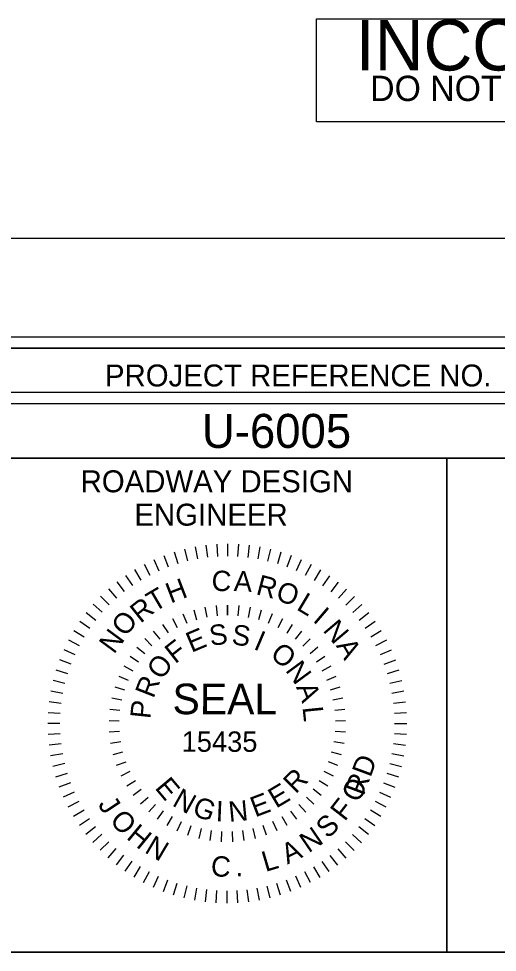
# Model space of a CAD drawing. Extents: x 1623313 to 1628771, y 891211 to 901910.
# Drawn here: x 1624782.4 to 1624891.5, y 901696.9 to 901909.5 of the extents above; entities that cross this region are included whole.
import ezdxf

# ---------------------------------------------------------------- set-up
doc = ezdxf.new("R2010")
doc.units = 0
for name, color, linetype in [('Old_Level_21', 7, 'Continuous'), ('Prop Plan Preparation Cover Label', 7, 'Continuous'), ('Scratch_Level_0', 7, 'Continuous'), ('Sheet Cutting Line CELL', 7, 'Continuous'), ('Sheet Data Field CELL', 7, 'Continuous'), ('Sheet Plot Border Inside CELL', 7, 'Continuous'), ('Sheet Plot Border Outside CELL', 7, 'Continuous'), ('Sheet Profile CELL', 7, 'Continuous'), ('Sheet Profile Grid Major CELL', 7, 'Continuous'), ('Sheet Profile Grid Minor CELL', 7, 'Continuous'), ('Sheet Sticker Exception Certification CELL', 7, 'Continuous')]:
    doc.layers.add(name, color=color, linetype=linetype)

msp = doc.modelspace()

# ---------------------------------------------------------------- linework, layer by layer
at = {"layer": 'Old_Level_21'}
for p, q in [((1624820.25, 901788.74), (1624820.9, 901786.03)), ((1624822.66, 901789.26), (1624823.16, 901786.51)), ((1624825.1, 901789.62), (1624825.43, 901786.86)), ((1624827.56, 901789.84), (1624827.73, 901787.06)), ((1624830.03, 901789.91), (1624830.03, 901787.13)), ((1624832.51, 901789.84), (1624832.33, 901787.05)), ((1624834.96, 901789.61), (1624834.63, 901786.84)), ((1624837.41, 901789.24), (1624836.9, 901786.49)), ((1624839.82, 901788.71), (1624839.15, 901786.01)), ((1624813.24, 901786.33), (1624814.38, 901783.79)), ((1624815.53, 901787.28), (1624816.51, 901784.67)), ((1624817.86, 901788.08), (1624818.69, 901785.41)), ((1624842.2, 901788.05), (1624841.37, 901785.38)), ((1624844.54, 901787.24), (1624843.54, 901784.63)), ((1624846.82, 901786.28), (1624845.67, 901783.75)), ((1624811.02, 901785.26), (1624812.31, 901782.78)), ((1624849.04, 901785.2), (1624847.74, 901782.73)), ((1624806.79, 901782.71), (1624808.37, 901780.41)), ((1624808.86, 901784.04), (1624810.3, 901781.66)), ((1624851.19, 901783.99), (1624849.74, 901781.6)), ((1624853.26, 901782.64), (1624851.67, 901780.35)), ((1624804.8, 901781.25), (1624806.51, 901779.05)), ((1624855.25, 901781.18), (1624853.53, 901778.98)), ((1624801.09, 901777.97), (1624803.06, 901776)), ((1624802.89, 901779.66), (1624804.74, 901777.58)), ((1624857.15, 901779.59), (1624855.29, 901777.51)), ((1624858.94, 901777.89), (1624856.97, 901775.92)), ((1624799.4, 901776.18), (1624801.48, 901774.33)), ((1624827.41, 901775.85), (1624827.63, 901773.53)), ((1624830.01, 901775.97), (1624830.01, 901773.65)), ((1624830.01, 901773.65), (1624830.01, 901775.97)), ((1624832.62, 901775.84), (1624832.39, 901773.53)), ((1624860.63, 901776.09), (1624858.54, 901774.25)), ((1624797.81, 901774.28), (1624800, 901772.56)), ((1624819.84, 901773.99), (1624820.72, 901771.84)), ((1624822.31, 901774.86), (1624822.96, 901772.63)), ((1624824.84, 901775.47), (1624825.28, 901773.19)), ((1624835.19, 901775.46), (1624834.75, 901773.18)), ((1624837.72, 901774.83), (1624837.06, 901772.61)), ((1624840.18, 901773.97), (1624839.3, 901771.81)), ((1624862.21, 901774.19), (1624860.02, 901772.48)), ((1624796.35, 901772.29), (1624798.64, 901770.71)), ((1624815.23, 901771.58), (1624816.5, 901769.63)), ((1624817.48, 901772.9), (1624818.56, 901770.84)), ((1624842.54, 901772.86), (1624841.46, 901770.81)), ((1624844.78, 901771.54), (1624843.51, 901769.6)), ((1624863.67, 901772.2), (1624861.38, 901770.62)), ((1624795, 901770.22), (1624797.38, 901768.77)), ((1624813.12, 901770.05), (1624814.58, 901768.24)), ((1624846.89, 901770.01), (1624845.43, 901768.19)), ((1624865.01, 901770.12), (1624862.63, 901768.68)), ((1624793.78, 901768.07), (1624796.25, 901766.77)), ((1624811.17, 901768.33), (1624812.8, 901766.66)), ((1624848.84, 901768.27), (1624847.21, 901766.61)), ((1624866.23, 901767.97), (1624863.75, 901766.68)), ((1624792.7, 901765.85), (1624795.24, 901764.7)), ((1624809.4, 901766.42), (1624811.17, 901764.92)), ((1624850.61, 901766.37), (1624848.83, 901764.87)), ((1624867.3, 901765.74), (1624864.76, 901764.61)), ((1624791.75, 901763.57), (1624794.36, 901762.57)), ((1624807.81, 901764.36), (1624809.72, 901763.03)), ((1624852.19, 901764.3), (1624850.27, 901762.97)), ((1624868.25, 901763.46), (1624865.64, 901762.47)), ((1624790.94, 901761.24), (1624793.6, 901760.4)), ((1624806.44, 901762.15), (1624808.46, 901761.01)), ((1624853.56, 901762.08), (1624851.53, 901760.95)), ((1624869.05, 901761.13), (1624866.38, 901760.3)), ((1624790.27, 901758.85), (1624792.98, 901758.19)), ((1624805.27, 901759.81), (1624807.4, 901758.88)), ((1624854.71, 901759.74), (1624852.58, 901758.82)), ((1624869.71, 901758.74), (1624867, 901758.08)), ((1624804.35, 901757.37), (1624806.56, 901756.66)), ((1624855.63, 901757.3), (1624853.42, 901756.59)), ((1624789.75, 901756.44), (1624792.49, 901755.93)), ((1624803.66, 901754.86), (1624805.93, 901754.36)), ((1624856.31, 901754.79), (1624854.04, 901754.29)), ((1624870.22, 901756.33), (1624867.48, 901755.83)), ((1624789.38, 901754), (1624792.14, 901753.66)), ((1624803.22, 901752.3), (1624805.52, 901752.02)), ((1624856.74, 901752.22), (1624854.44, 901751.95)), ((1624870.59, 901753.88), (1624867.82, 901753.55)), ((1624789.15, 901751.54), (1624791.93, 901751.37)), ((1624870.81, 901751.42), (1624868.03, 901751.26)), ((1624789.07, 901749.07), (1624791.86, 901749.06)), ((1624803.03, 901749.7), (1624805.35, 901749.64)), ((1624856.93, 901749.62), (1624854.61, 901749.57)), ((1624870.88, 901748.95), (1624868.09, 901748.96)), ((1624789.14, 901746.59), (1624791.93, 901746.76)), ((1624803.08, 901747.09), (1624805.4, 901747.26)), ((1624856.86, 901747.02), (1624854.55, 901747.19)), ((1624870.8, 901746.48), (1624868.02, 901746.65)), ((1624789.37, 901744.13), (1624792.13, 901744.47)), ((1624803.4, 901744.51), (1624805.69, 901744.9)), ((1624854.27, 901744.91), (1624856.56, 901744.52)), ((1624870.58, 901744.02), (1624867.81, 901744.36)), ((1624789.73, 901741.69), (1624792.47, 901742.19)), ((1624803.95, 901741.96), (1624806.19, 901742.57)), ((1624855.98, 901741.89), (1624853.74, 901742.5)), ((1624870.2, 901741.58), (1624867.46, 901742.08)), ((1624790.25, 901739.28), (1624792.95, 901739.94)), ((1624804.76, 901739.48), (1624806.93, 901740.3)), ((1624855.17, 901739.41), (1624853, 901740.24)), ((1624869.68, 901739.17), (1624866.98, 901739.83)), ((1624790.9, 901736.89), (1624793.57, 901737.72)), ((1624805.8, 901737.1), (1624807.88, 901738.12)), ((1624854.13, 901737.03), (1624852.05, 901738.06)), ((1624869.02, 901736.78), (1624866.35, 901737.62)), ((1624791.71, 901734.56), (1624794.32, 901735.54)), ((1624807.05, 901734.82), (1624809.03, 901736.04)), ((1624852.86, 901734.75), (1624850.89, 901735.98)), ((1624868.21, 901734.45), (1624865.6, 901735.45)), ((1624792.65, 901732.27), (1624795.2, 901733.41)), ((1624808.53, 901732.67), (1624810.38, 901734.08)), ((1624851.38, 901732.61), (1624849.53, 901734.02)), ((1624867.25, 901732.17), (1624864.71, 901733.32)), ((1624793.73, 901730.05), (1624796.2, 901731.34)), ((1624810.21, 901730.68), (1624811.91, 901732.25)), ((1624849.69, 901730.62), (1624848, 901732.2)), ((1624866.17, 901729.95), (1624863.7, 901731.25)), ((1624794.94, 901727.89), (1624797.33, 901729.34)), ((1624812.07, 901728.86), (1624813.62, 901730.59)), ((1624814.1, 901727.22), (1624815.47, 901729.1)), ((1624845.79, 901727.18), (1624844.43, 901729.06)), ((1624847.83, 901728.81), (1624846.29, 901730.55)), ((1624864.95, 901727.8), (1624862.57, 901729.25)), ((1624796.28, 901725.82), (1624798.58, 901727.4)), ((1624816.28, 901725.79), (1624817.46, 901727.79)), ((1624843.61, 901725.75), (1624842.44, 901727.76)), ((1624863.61, 901725.72), (1624861.32, 901727.31)), ((1624797.74, 901723.83), (1624799.94, 901725.54)), ((1624818.58, 901724.58), (1624819.57, 901726.68)), ((1624821, 901723.59), (1624821.77, 901725.78)), ((1624824.03, 901725.1), (1624823.47, 901722.84)), ((1624826.05, 901722.34), (1624826.38, 901724.64)), ((1624833.83, 901722.33), (1624833.5, 901724.63)), ((1624836.39, 901722.82), (1624835.84, 901725.08)), ((1624838.89, 901723.56), (1624838.12, 901725.76)), ((1624841.3, 901724.55), (1624840.33, 901726.66)), ((1624862.14, 901723.74), (1624859.95, 901725.46)), ((1624799.32, 901721.93), (1624801.41, 901723.77)), ((1624828.64, 901722.08), (1624828.75, 901724.4)), ((1624831.24, 901722.08), (1624831.14, 901724.4)), ((1624860.56, 901721.84), (1624858.47, 901723.69)), ((1624801.01, 901720.13), (1624802.99, 901722.09)), ((1624802.81, 901718.43), (1624804.66, 901720.51)), ((1624857.06, 901718.35), (1624855.21, 901720.44)), ((1624858.86, 901720.05), (1624856.89, 901722.02)), ((1624804.71, 901716.84), (1624806.43, 901719.04)), ((1624855.16, 901716.77), (1624853.44, 901718.97)), ((1624806.69, 901715.38), (1624808.28, 901717.67)), ((1624808.76, 901714.03), (1624810.21, 901716.42)), ((1624851.09, 901713.97), (1624849.65, 901716.36)), ((1624853.17, 901715.31), (1624851.59, 901717.61)), ((1624810.92, 901712.81), (1624812.22, 901715.28)), ((1624813.14, 901711.73), (1624814.28, 901714.27)), ((1624846.71, 901711.69), (1624845.57, 901714.23)), ((1624848.94, 901712.76), (1624847.64, 901715.23)), ((1624815.42, 901710.78), (1624816.41, 901713.39)), ((1624817.75, 901709.97), (1624818.58, 901712.64)), ((1624820.13, 901709.3), (1624820.8, 901712.01)), ((1624839.71, 901709.28), (1624839.05, 901711.99)), ((1624842.09, 901709.94), (1624841.27, 901712.6)), ((1624844.43, 901710.74), (1624843.44, 901713.35)), ((1624822.55, 901708.78), (1624823.05, 901711.52)), ((1624824.99, 901708.41), (1624825.33, 901711.18)), ((1624827.45, 901708.18), (1624827.62, 901710.96)), ((1624829.92, 901708.1), (1624829.92, 901710.89)), ((1624832.39, 901708.18), (1624832.23, 901710.96)), ((1624834.85, 901708.4), (1624834.52, 901711.16)), ((1624837.29, 901708.76), (1624836.8, 901711.5))]:
    msp.add_line(p, q, dxfattribs=at)
at = {"layer": 'Prop Plan Preparation Cover Label'}
msp.add_lwpolyline([(1624850.31, 901886.02), (1624850.31, 901909.52), (1624997.31, 901909.52), (1624997.31, 901886.02)], close=True, dxfattribs=at)
at = {"layer": 'Scratch_Level_0'}
msp.add_lwpolyline([(1623529.95, 901824.45), (1624929.95, 901824.45), (1624929.95, 901334.45), (1623529.95, 901334.45)], close=True, dxfattribs=at)
at = {"layer": 'Sheet Cutting Line CELL'}
msp.add_line((1624996.95, 901859.45), (1623312.95, 901859.45), dxfattribs=at)
at = {"layer": 'Sheet Plot Border Inside CELL'}
msp.add_lwpolyline([(1623325.95, 900781.9), (1624992.45, 900781.9), (1624992.45, 901837), (1623325.95, 901837)], close=True, dxfattribs=at)
at = {"layer": 'Sheet Plot Border Outside CELL'}
msp.add_lwpolyline([(1623312.95, 900759.45), (1624996.95, 900759.45), (1624996.95, 901859.45), (1623312.95, 901859.45)], close=True, dxfattribs=at)
at = {"layer": 'Sheet Profile CELL'}
for p, q in [((1624779.9, 901821.9), (1624979.95, 901821.9)), ((1624879.95, 901809.4), (1624879.95, 901696.95))]:
    msp.add_line(p, q, dxfattribs=at)
for points in [[(1624979.95, 901834.45), (1623479.95, 901834.45), (1623479.95, 900784.45), (1624979.95, 900784.45)], [(1624779.9, 901834.45), (1624979.95, 901834.45), (1624979.95, 901809.4), (1624779.9, 901809.4)], [(1624779.9, 901809.4), (1624879.95, 901809.4), (1624879.95, 901696.9), (1624779.9, 901696.9)], [(1624879.95, 901809.4), (1624979.95, 901809.4), (1624979.95, 901696.9), (1624879.95, 901696.9)]]:
    msp.add_lwpolyline(points, close=True, dxfattribs=at)
at = {"layer": 'Sheet Profile Grid Major CELL'}
msp.add_lwpolyline([(1624779.95, 901834.45), (1624806.25, 901834.45)], dxfattribs=at)
at = {"layer": 'Sheet Profile Grid Minor CELL'}
msp.add_lwpolyline([(1624774.95, 901834.45), (1624784.95, 901834.45)], dxfattribs=at)
at = {"layer": 'Sheet Sticker Exception Certification CELL'}
msp.add_line((1624779.9, 901696.9), (1624979.93, 901696.9), dxfattribs=at)
msp.add_line((1624779.9, 901696.9), (1624979.93, 901696.9), dxfattribs=at)

# ---------------------------------------------------------------- texts
at = {"layer": 'Old_Level_21'}
for s, height, rotation, p in [('H', 4.64, 20.9878, (1624817.06, 901776.3)), ('C', 4.64, 357.2771, (1624826.3, 901779.27)), ('A', 4.64, 357.2771, (1624831.38, 901779.17)), ('R', 4.64, 345.2678, (1624836.3, 901778.48)), ('T', 4.64, 30.4198, (1624813.32, 901774.29)), ('O', 4.64, 342.211, (1624840.79, 901777.14)), ('L', 4.64, 329.0747, (1624845.51, 901775.07)), ('R', 4.64, 38.5807, (1624810.19, 901771.69)), ('O', 4.64, 51.6375, (1624806.82, 901768.57)), ('I', 4.64, 319.4993, (1624849.26, 901772.36)), ('S', 4.64, 7.5683, (1624826.17, 901766.67)), ('S', 4.64, 352.272, (1624830.81, 901767.05)), ('N', 4.64, 310.2048, (1624851.58, 901770.17)), ('N', 4.64, 53.5969, (1624804.15, 901764.65)), ('E', 4.64, 22.8645, (1624821.81, 901765.08)), ('I', 4.64, 336.9758, (1624835.74, 901766.04)), ('F', 4.64, 38.1608, (1624818.09, 901762.46)), ('A', 4.64, 300.4373, (1624854.64, 901766.74)), ('O', 4.64, 321.6795, (1624839.49, 901764.23)), ('O', 4.64, 53.457, (1624815, 901758.72)), ('N', 4.64, 306.3833, (1624843.06, 901761.11)), ('R', 4.64, 68.7533, (1624813.15, 901754.55)), ('SEAL', 6.97, 359.9202, (1624817.49, 901751.12)), ('A', 4.64, 291.0871, (1624845.6, 901757.31)), ('P', 4.64, 84.0495, (1624812.44, 901749.95)), ('L', 4.64, 275.7908, (1624847.1, 901752.71)), ('15435', 4.643, 359.9202, (1624819.57, 901742.57)), (' RD', 4.643, 69.5926, (1624860.42, 901730.76)), ('R', 4.64, 44.4851, (1624845.51, 901732.81)), ('E', 4.64, 309.9903, (1624813.31, 901734.29)), ('E', 4.64, 30.714, (1624841.08, 901729.58)), ('O ', 4.643, 60.9198, (1624859.75, 901730.74)), ('N', 4.64, 330.8453, (1624817.21, 901730.41)), ('E', 4.64, 20.7281, (1624836.31, 901727.6)), ('J', 4.64, 303.8552, (1624800.36, 901730.51)), ('G', 4.64, 339.6116, (1624821.75, 901728.23)), ('I', 4.64, 357.7064, (1624827.28, 901726.73)), ('N', 4.64, 5.336, (1624830.43, 901726.57)), ('F', 4.64, 52.1272, (1624856.72, 901726.55)), ('O', 4.64, 311.927, (1624803, 901726.81)), ('S', 4.64, 43.2446, (1624852.85, 901722.61)), ('H', 4.64, 320.5697, (1624806.79, 901722.89)), ('N', 4.64, 34.362, (1624848.5, 901719.4)), ('N', 4.64, 329.2423, (1624810.9, 901719.75)), ('A', 4.64, 25.5393, (1624843.67, 901716.87)), ('C', 4.64, 356.0101, (1624826.12, 901714.29)), ('L', 4.64, 16.5368, (1624838.65, 901715.18)), ('.', 4.64, 3.7525, (1624831.89, 901714.16))]:
    msp.add_text(s, height=height, rotation=rotation, dxfattribs=at).set_placement(p)
at = {"layer": 'Prop Plan Preparation Cover Label'}
for s, height, p in [('INCOMPLETE PLANS', 11.52, (1624859.26, 901897.72)), ('DO NOT USE FOR R/W ACQUISITION', 5.76, (1624862.51, 901890.77))]:
    msp.add_text(s, height=height, dxfattribs=at).set_placement(p)
at = {"layer": 'Sheet Data Field CELL'}
msp.add_text('U-6005', height=7.75, dxfattribs=at).set_placement((1624824.19, 901811.76))
at = {"layer": 'Sheet Profile CELL'}
for s, height, p in [('PROJECT REFERENCE NO.', 5.0001, (1624802.11, 901825.76)), ('ROADWAY DESIGN', 5.0001, (1624796.56, 901801.66)), ('ENGINEER', 5, (1624808.81, 901794.06))]:
    msp.add_text(s, height=height, dxfattribs=at).set_placement(p)

doc.saveas('drawing.dxf')
